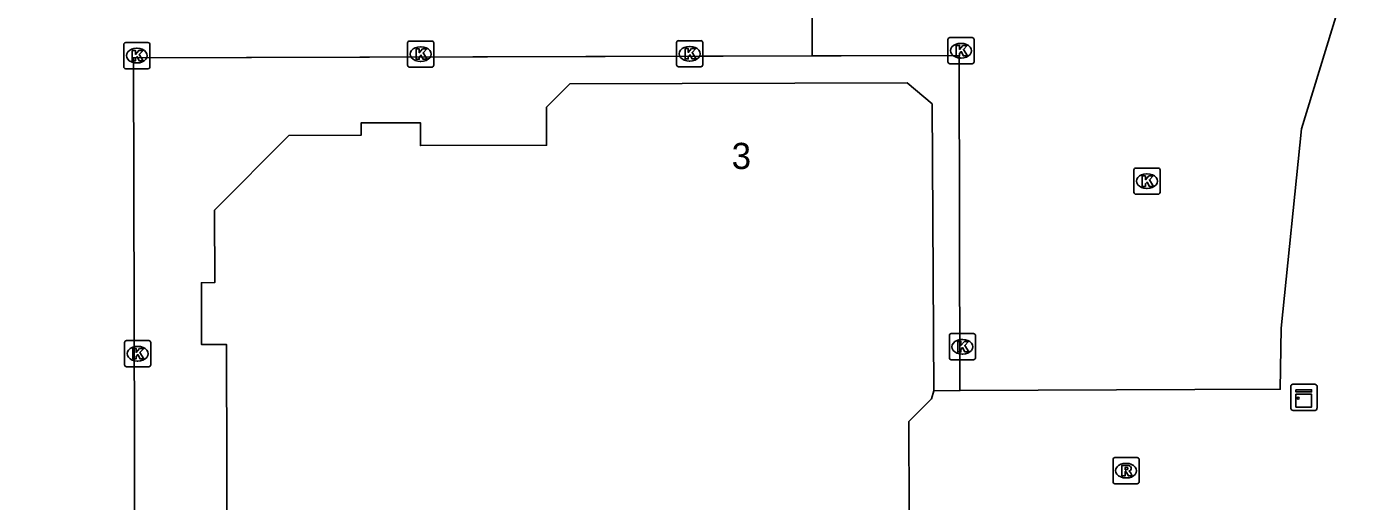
# Model space of a CAD drawing. Extents: x 160203 to 161526, y 379529 to 381797.
# Drawn here: x 160867.9 to 160918.7, y 380731.2 to 380749.3 of the extents above; entities that cross this region are included whole.
import ezdxf

# ---------------------------------------------------------------- set-up
doc = ezdxf.new("R2010")
doc.units = 0
for name, color, linetype in [('IMGEO_Kast', 7, 'Continuous'), ('IMGEO_Kolk', 7, 'Continuous'), ('IMGEO_Pand', 7, 'Continuous'), ('IMGEO_Pand_nummerreeks', 7, 'Continuous'), ('IMGEO_Pand_overbouw', 7, 'Continuous'), ('IMGEO_Rioolput', 7, 'Continuous'), ('IMGEO_Voetpad_open', 7, 'Continuous')]:
    doc.layers.add(name, color=color, linetype=linetype)

msp = doc.modelspace()

# ---------------------------------------------------------------- linework, layer by layer
at = {"layer": 'IMGEO_Kast'}
for p, q in [((160916.346, 380734.732), (160916.346, 380735.573)), ((160916.346, 380735.573), (160916.346, 380734.732)), ((160916.421, 380735.657), (160917.262, 380735.657)), ((160917.262, 380735.657), (160916.421, 380735.657)), ((160917.346, 380735.582), (160917.346, 380734.741)), ((160917.346, 380734.741), (160917.346, 380735.582)), ((160917.271, 380734.657), (160916.43, 380734.657)), ((160916.43, 380734.657), (160917.271, 380734.657))]:
    msp.add_line(p, q, dxfattribs=at)
for points in [[(160916.541, 380735.447), (160917.141, 380735.447), (160917.141, 380735.362), (160916.541, 380735.362), (160916.541, 380735.447)], [(160916.541, 380735.272), (160917.141, 380735.272), (160917.141, 380734.783), (160916.541, 380734.783), (160916.541, 380735.272)]]:
    msp.add_lwpolyline(points, dxfattribs=at)
msp.add_circle((160916.625, 380735.121), 0.0377, dxfattribs=at)
for centre, start, end in [((160916.424, 380735.579), 92.4484, 184.2845), ((160916.424, 380735.579), 92.4484, 184.2845), ((160917.268, 380735.579), 2.4484, 94.2845), ((160917.268, 380735.579), 2.4484, 94.2845), ((160916.424, 380734.735), 182.4484, 274.2845), ((160916.424, 380734.735), 182.4484, 274.2845), ((160917.268, 380734.735), 272.4484, 4.2845), ((160917.268, 380734.735), 272.4484, 4.2845)]:
    msp.add_arc(centre, 0.0779, start, end, dxfattribs=at)
at = {"layer": 'IMGEO_Kolk'}
for p, q in [((160882.601, 380748.787), (160883.453, 380748.787)), ((160892.901, 380748.8), (160893.753, 380748.8)), ((160903.214, 380747.991), (160903.214, 380748.843)), ((160903.289, 380748.917), (160904.141, 380748.917)), ((160904.215, 380748.843), (160904.215, 380747.991)), ((160871.657, 380747.802), (160871.657, 380748.654)), ((160871.732, 380748.728), (160872.584, 380748.728)), ((160872.145, 380748.508), (160872.17, 380748.508)), ((160872.658, 380748.654), (160872.658, 380747.802)), ((160882.526, 380747.861), (160882.526, 380748.713)), ((160883.014, 380748.567), (160883.039, 380748.567)), ((160883.527, 380748.713), (160883.527, 380747.861)), ((160892.826, 380747.874), (160892.826, 380748.726)), ((160893.314, 380748.58), (160893.339, 380748.58)), ((160893.827, 380748.726), (160893.827, 380747.874)), ((160903.702, 380748.697), (160903.727, 380748.697)), ((160872.168, 380747.948), (160872.143, 380747.948)), ((160883.453, 380747.787), (160882.601, 380747.787)), ((160883.037, 380748.007), (160883.012, 380748.007)), ((160893.753, 380747.8), (160892.901, 380747.8)), ((160893.337, 380748.02), (160893.312, 380748.02)), ((160904.141, 380747.917), (160903.289, 380747.917)), ((160903.725, 380748.137), (160903.7, 380748.137)), ((160872.584, 380747.728), (160871.732, 380747.728)), ((160910.334, 380743.002), (160910.334, 380743.854)), ((160910.409, 380743.928), (160911.261, 380743.928)), ((160910.822, 380743.708), (160910.847, 380743.708)), ((160911.335, 380743.854), (160911.335, 380743.002)), ((160911.261, 380742.928), (160910.409, 380742.928)), ((160910.845, 380743.148), (160910.82, 380743.148)), ((160903.344, 380737.593), (160904.196, 380737.593)), ((160871.686, 380736.4), (160871.686, 380737.252)), ((160871.761, 380737.326), (160872.613, 380737.326)), ((160872.174, 380737.106), (160872.199, 380737.106)), ((160872.687, 380737.252), (160872.687, 380736.4)), ((160903.269, 380736.667), (160903.269, 380737.519)), ((160903.757, 380737.373), (160903.782, 380737.373)), ((160904.27, 380737.519), (160904.27, 380736.667)), ((160904.196, 380736.593), (160903.344, 380736.593)), ((160903.78, 380736.813), (160903.755, 380736.813)), ((160872.613, 380736.326), (160871.761, 380736.326)), ((160872.197, 380736.546), (160872.172, 380736.546))]:
    msp.add_line(p, q, dxfattribs=at)
for points in [[(160882.601, 380748.787), (160883.453, 380748.787)], [(160892.901, 380748.8), (160893.753, 380748.8)], [(160903.214, 380747.991), (160903.214, 380748.843)], [(160903.289, 380748.917), (160904.141, 380748.917)], [(160904.215, 380748.843), (160904.215, 380747.991)], [(160871.657, 380747.802), (160871.657, 380748.654)], [(160871.732, 380748.728), (160872.584, 380748.728)], [(160871.978, 380748.428), (160872.101, 380748.428), (160872.101, 380748.277), (160872.231, 380748.428), (160872.395, 380748.428), (160872.249, 380748.277), (160872.402, 380748.028), (160872.25, 380748.028), (160872.165, 380748.192), (160872.101, 380748.125), (160872.101, 380748.028), (160871.978, 380748.028), (160871.978, 380748.428)], [(160872.658, 380748.654), (160872.658, 380747.802)], [(160882.526, 380747.861), (160882.526, 380748.713)], [(160882.847, 380748.487), (160882.97, 380748.487), (160882.97, 380748.336), (160883.1, 380748.487), (160883.264, 380748.487), (160883.118, 380748.336), (160883.271, 380748.087), (160883.119, 380748.087), (160883.034, 380748.251), (160882.97, 380748.184), (160882.97, 380748.087), (160882.847, 380748.087), (160882.847, 380748.487)], [(160883.527, 380748.713), (160883.527, 380747.861)], [(160892.826, 380747.874), (160892.826, 380748.726)], [(160893.147, 380748.5), (160893.27, 380748.5), (160893.27, 380748.349), (160893.4, 380748.5), (160893.564, 380748.5), (160893.418, 380748.349), (160893.571, 380748.1), (160893.419, 380748.1), (160893.334, 380748.264), (160893.27, 380748.197), (160893.27, 380748.1), (160893.147, 380748.1), (160893.147, 380748.5)], [(160893.827, 380748.726), (160893.827, 380747.874)], [(160903.535, 380748.617), (160903.658, 380748.617), (160903.658, 380748.466), (160903.788, 380748.617), (160903.952, 380748.617), (160903.806, 380748.466), (160903.959, 380748.217), (160903.807, 380748.217), (160903.722, 380748.381), (160903.658, 380748.314), (160903.658, 380748.217), (160903.535, 380748.217), (160903.535, 380748.617)], [(160883.453, 380747.787), (160882.601, 380747.787)], [(160893.753, 380747.8), (160892.901, 380747.8)], [(160904.141, 380747.917), (160903.289, 380747.917)], [(160872.584, 380747.728), (160871.732, 380747.728)], [(160910.334, 380743.002), (160910.334, 380743.854)], [(160910.409, 380743.928), (160911.261, 380743.928)], [(160911.335, 380743.854), (160911.335, 380743.002)], [(160910.655, 380743.628), (160910.778, 380743.628), (160910.778, 380743.477), (160910.908, 380743.628), (160911.072, 380743.628), (160910.926, 380743.477), (160911.079, 380743.228), (160910.927, 380743.228), (160910.842, 380743.392), (160910.778, 380743.325), (160910.778, 380743.228), (160910.655, 380743.228), (160910.655, 380743.628)], [(160911.261, 380742.928), (160910.409, 380742.928)], [(160903.344, 380737.593), (160904.196, 380737.593)], [(160871.686, 380736.4), (160871.686, 380737.252)], [(160871.761, 380737.326), (160872.613, 380737.326)], [(160872.687, 380737.252), (160872.687, 380736.4)], [(160903.269, 380736.667), (160903.269, 380737.519)], [(160903.59, 380737.293), (160903.713, 380737.293), (160903.713, 380737.142), (160903.843, 380737.293), (160904.007, 380737.293), (160903.861, 380737.142), (160904.014, 380736.893), (160903.862, 380736.893), (160903.777, 380737.057), (160903.713, 380736.99), (160903.713, 380736.893), (160903.59, 380736.893), (160903.59, 380737.293)], [(160904.27, 380737.519), (160904.27, 380736.667)], [(160872.007, 380737.026), (160872.13, 380737.026), (160872.13, 380736.875), (160872.26, 380737.026), (160872.424, 380737.026), (160872.278, 380736.875), (160872.431, 380736.626), (160872.279, 380736.626), (160872.194, 380736.79), (160872.13, 380736.723), (160872.13, 380736.626), (160872.007, 380736.626), (160872.007, 380737.026)], [(160904.196, 380736.593), (160903.344, 380736.593)], [(160872.613, 380736.326), (160871.761, 380736.326)]]:
    msp.add_lwpolyline(points, dxfattribs=at)
for centre, start, end in [((160882.603, 380748.711), 91.552, 178.448), ((160882.603, 380748.711), 91.552, 178.448), ((160883.451, 380748.711), 1.552, 88.448), ((160883.451, 380748.711), 1.552, 88.448), ((160892.903, 380748.724), 91.552, 178.448), ((160892.903, 380748.724), 91.552, 178.448), ((160893.751, 380748.724), 1.552, 88.448), ((160893.751, 380748.724), 1.552, 88.448), ((160903.291, 380748.841), 91.552, 178.448), ((160903.291, 380748.841), 91.552, 178.448), ((160904.139, 380748.841), 1.552, 88.448), ((160904.139, 380748.841), 1.552, 88.448), ((160871.734, 380748.652), 91.552, 178.448), ((160871.734, 380748.652), 91.552, 178.448), ((160872.582, 380748.652), 1.552, 88.448), ((160872.582, 380748.652), 1.552, 88.448), ((160871.734, 380747.804), 181.552, 268.448), ((160871.734, 380747.804), 181.552, 268.448), ((160872.582, 380747.804), 271.552, 358.448), ((160872.582, 380747.804), 271.552, 358.448), ((160882.603, 380747.863), 181.552, 268.448), ((160882.603, 380747.863), 181.552, 268.448), ((160883.451, 380747.863), 271.552, 358.448), ((160883.451, 380747.863), 271.552, 358.448), ((160892.903, 380747.876), 181.552, 268.448), ((160892.903, 380747.876), 181.552, 268.448), ((160893.751, 380747.876), 271.552, 358.448), ((160893.751, 380747.876), 271.552, 358.448), ((160903.291, 380747.993), 181.552, 268.448), ((160903.291, 380747.993), 181.552, 268.448), ((160904.139, 380747.993), 271.552, 358.448), ((160904.139, 380747.993), 271.552, 358.448), ((160910.411, 380743.852), 91.552, 178.448), ((160910.411, 380743.852), 91.552, 178.448), ((160911.259, 380743.852), 1.552, 88.448), ((160911.259, 380743.852), 1.552, 88.448), ((160910.411, 380743.004), 181.552, 268.448), ((160910.411, 380743.004), 181.552, 268.448), ((160911.259, 380743.004), 271.552, 358.448), ((160911.259, 380743.004), 271.552, 358.448), ((160903.346, 380737.517), 91.552, 178.448), ((160903.346, 380737.517), 91.552, 178.448), ((160904.194, 380737.517), 1.552, 88.448), ((160904.194, 380737.517), 1.552, 88.448), ((160871.763, 380737.25), 91.552, 178.448), ((160871.763, 380737.25), 91.552, 178.448), ((160872.611, 380737.25), 1.552, 88.448), ((160872.611, 380737.25), 1.552, 88.448), ((160903.346, 380736.669), 181.552, 268.448), ((160903.346, 380736.669), 181.552, 268.448), ((160904.194, 380736.669), 271.552, 358.448), ((160904.194, 380736.669), 271.552, 358.448), ((160871.763, 380736.402), 181.552, 268.448), ((160871.763, 380736.402), 181.552, 268.448), ((160872.611, 380736.402), 271.552, 358.448), ((160872.611, 380736.402), 271.552, 358.448)]:
    msp.add_arc(centre, 0.0765, start, end, dxfattribs=at)
for centre, major_axis, ratio, start_param, end_param in [((160872.144, 380748.228), (-0.387, 0.002), 0.722429, 4.712389, 7.853982), ((160872.169, 380748.228), (-0.39, 0.002), 0.717154, 1.570796, 4.712389), ((160883.013, 380748.287), (-0.387, 0.002), 0.722429, 4.712389, 7.853982), ((160883.038, 380748.287), (-0.39, 0.002), 0.717154, 1.570796, 4.712389), ((160893.313, 380748.3), (-0.387, 0.002), 0.722429, 4.712389, 7.853982), ((160893.338, 380748.3), (-0.39, 0.002), 0.717154, 1.570796, 4.712389), ((160903.701, 380748.417), (-0.387, 0.002), 0.722429, 4.712389, 7.853982), ((160903.726, 380748.417), (-0.39, 0.002), 0.717154, 1.570796, 4.712389), ((160910.821, 380743.428), (-0.387, 0.002), 0.722429, 4.712389, 7.853982), ((160910.846, 380743.428), (-0.39, 0.002), 0.717154, 1.570796, 4.712389), ((160872.173, 380736.826), (-0.387, 0.002), 0.722429, 4.712389, 7.853982), ((160872.198, 380736.826), (-0.39, 0.002), 0.717154, 1.570796, 4.712389), ((160903.756, 380737.093), (-0.387, 0.002), 0.722429, 4.712389, 7.853982), ((160903.781, 380737.093), (-0.39, 0.002), 0.717154, 1.570796, 4.712389)]:
    msp.add_ellipse(centre, major_axis=major_axis, ratio=ratio, start_param=start_param, end_param=end_param, dxfattribs=at)
at = {"layer": 'IMGEO_Pand'}
for points in [[(160918.998, 380752.751), (160918.433, 380750.903), (160918.157, 380750), (160916.758, 380745.422), (160915.974, 380737.805), (160915.94, 380735.467), (160912.662, 380735.453), (160903.673, 380735.416)], [(160902.67, 380735.412), (160902.609, 380746.38), (160901.659, 380747.188), (160888.743, 380747.155), (160887.844, 380746.251), (160887.848, 380744.803), (160883.018, 380744.79), (160883.015, 380745.662), (160880.743, 380745.657), (160880.744, 380745.18), (160877.98, 380745.173), (160875.134, 380742.312), (160875.142, 380739.544), (160874.628, 380739.543), (160874.635, 380737.172), (160875.597, 380737.175), (160875.647, 380717.982), (160873.953, 380717.977), (160873.299, 380717.32), (160873.315, 380711), (160844.279, 380710.924), (160844.274, 380712.634)], [(160902.67, 380735.412), (160902.579, 380735.097), (160901.722, 380734.236), (160901.731, 380730.795), (160903.685, 380730.806)], [(160903.673, 380735.416), (160902.67, 380735.412)]]:
    msp.add_lwpolyline(points, dxfattribs=at)
at = {"layer": 'IMGEO_Pand_overbouw'}
msp.add_lwpolyline([(160875.647, 380717.982), (160875.597, 380737.175), (160874.635, 380737.172), (160874.628, 380739.543), (160875.142, 380739.544), (160875.134, 380742.312), (160877.98, 380745.173), (160880.744, 380745.18), (160880.743, 380745.657), (160883.015, 380745.662), (160883.018, 380744.79), (160887.848, 380744.803), (160887.844, 380746.251), (160888.743, 380747.155), (160901.659, 380747.188), (160902.609, 380746.38), (160902.67, 380735.412), (160903.673, 380735.416), (160903.639, 380748.231), (160872.029, 380748.148), (160872.107, 380718.502)], dxfattribs=at)
at = {"layer": 'IMGEO_Rioolput'}
for p, q in [((160909.536, 380731.926), (160909.536, 380732.778)), ((160909.611, 380732.852), (160910.463, 380732.852)), ((160910.024, 380732.632), (160910.049, 380732.632)), ((160910.537, 380732.778), (160910.537, 380731.926)), ((160910.047, 380732.072), (160910.022, 380732.072)), ((160910.463, 380731.852), (160909.611, 380731.852))]:
    msp.add_line(p, q, dxfattribs=at)
for points in [[(160909.536, 380731.926), (160909.536, 380732.778)], [(160909.611, 380732.852), (160910.463, 380732.852)], [(160910.125, 380732.55), (160909.873, 380732.552), (160909.873, 380732.152)], [(160910.537, 380732.778), (160910.537, 380731.926)], [(160909.873, 380732.152), (160909.997, 380732.152), (160909.997, 380732.314), (160910.008, 380732.314)], [(160910.051, 380732.471), (160909.997, 380732.471), (160909.997, 380732.39)], [(160909.997, 380732.39), (160910.049, 380732.39)], [(160910.055, 380732.285), (160910.126, 380732.152), (160910.266, 380732.152), (160910.201, 380732.278)], [(160910.463, 380731.852), (160909.611, 380731.852)]]:
    msp.add_lwpolyline(points, dxfattribs=at)
for centre, radius, start, end in [((160909.613, 380732.776), 0.0765, 91.552, 178.448), ((160909.613, 380732.776), 0.0765, 91.552, 178.448), ((160910.124, 380732.44), 0.109, 350.3612, 89.416), ((160910.461, 380732.776), 0.0765, 1.552, 88.448), ((160910.461, 380732.776), 0.0765, 1.552, 88.448), ((160910.007, 380732.261), 0.0533, 26.0293, 88.6989), ((160910.033, 380732.579), 0.19, 274.7715, 282.9687), ((160910.057, 380732.375), 0.0964, 77.0061, 93.1865), ((160910.071, 380732.432), 0.0378, 276.6634, 79.6772), ((160910.122, 380732.44), 0.112, 277.5842, 350.9817), ((160910.106, 380732.225), 0.108, 29.5134, 73.7905), ((160909.613, 380731.928), 0.0765, 181.552, 268.448), ((160909.613, 380731.928), 0.0765, 181.552, 268.448), ((160910.461, 380731.928), 0.0765, 271.552, 358.448), ((160910.461, 380731.928), 0.0765, 271.552, 358.448)]:
    msp.add_arc(centre, radius, start, end, dxfattribs=at)
for centre, major_axis, ratio, start_param, end_param in [((160910.023, 380732.352), (-0.387, 0.002), 0.722429, 4.712389, 7.853982), ((160910.048, 380732.352), (-0.39, 0.002), 0.717154, 1.570796, 4.712389)]:
    msp.add_ellipse(centre, major_axis=major_axis, ratio=ratio, start_param=start_param, end_param=end_param, dxfattribs=at)
at = {"layer": 'IMGEO_Voetpad_open'}
for points in [[(160898.017, 380748.216), (160898.019, 380750), (160898.011, 380750.632)], [(160872.107, 380718.502), (160872.029, 380748.148), (160898.017, 380748.216)], [(160898.017, 380748.216), (160903.639, 380748.231), (160903.673, 380735.416)]]:
    msp.add_lwpolyline(points, dxfattribs=at)

# ---------------------------------------------------------------- texts
at = {"layer": 'IMGEO_Pand_nummerreeks'}
msp.add_text('3', height=1, rotation=0.1464, dxfattribs=at).set_placement((160894.934, 380743.891))

doc.saveas('drawing.dxf')
